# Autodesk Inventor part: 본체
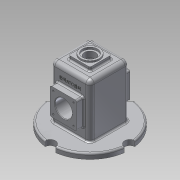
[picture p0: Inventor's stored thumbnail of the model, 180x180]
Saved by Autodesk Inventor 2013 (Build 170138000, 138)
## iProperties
Created: 2018-07
Part Number: 본체
Material: 알루미늄 6061
Document SubType Name: Modeling
Designer: Administrator
Mass: 1064.39 g
Surface Area: 1002.79 cm^2
Volume: 392.762 cm^3
Density: 2.71 g/cm^3
Author: Administrator
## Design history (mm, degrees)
sketch "스케치1"
  geometry: L1 (-37, -37)-(37, -37); L2 (37, -37)-(37, 37); L3 (37, 37)-(-37, 37); L4 (-37, 37)-(-37, -37); L5 (-37, -37)-(37, 37); L6 (37, -37)-(-37, 37); 1 further point
  constraints: 12 end point, 2 midpoint, 2 parallel, 1 horizontal, 1 perpendicular
  dimensions: "d0" = 74 distance of L2.end L3.end; "d2" = 74 distance of L1.end L2.end
extrude "돌출1" new body sketch "스케치1" distance "d3" = 110; taper "d4" = 0 deg
feature "쉘1" dims "d5" = 5
sketch "스케치2"
  geometry: L1 (0, 0)-(74, 0) reference; L2 (74, 0)-(74, 110) reference; L3 (12, 30)-(62, 30); L4 (62, 30)-(62, 80); L5 (62, 80)-(12, 80); L6 (12, 80)-(12, 30); L7 (12, 30)-(62, 80); L8 (62, 30)-(12, 80); 2 further points
  constraints: 12 end point, 2 midpoint, 2 parallel, 1 horizontal, 1 perpendicular
  dimensions: "d6" = 37 distance from line of L2 point (37, 55); "d7" = 55 distance from line of L1 point (37, 55); "d8" = 50 distance of L4.end L5.end; "d9" = 50 distance of L5.end L3.start
extrude "돌출2" join sketch "스케치2" distance "d10" = 13; taper "d11" = 0 deg
node "작업 평면1"
sketch "스케치3"
  geometry: L1 (20, -20)-(-20, -20); L2 (-20, -20)-(-20, 20); L3 (-20, 20)-(20, 20); L4 (20, 20)-(20, -20); L5 (20, -20)-(-20, 20); L6 (-20, -20)-(20, 20); 4 further points
  constraints: 12 end point, 4 midpoint, 2 coincident, 2 parallel, 1 horizontal, 1 perpendicular
  dimensions: "d12" = 40 distance of L1.end L2.end; "d14" = 40 distance of L2.end L3.end
extrude "돌출3" join sketch "스케치3" distance "d15" = 7; taper "d16" = 0 deg
sketch "스케치4"
  geometry: C1 r 17.5 at (0, 0); 1 further point
  constraints: 1 centre point, 1 coincident
  dimensions: "d17" = 35 diameter of C1
extrude "돌출4" join sketch "스케치4" distance "d19" = 3; taper "d20" = 0 deg
sketch "스케치5"
  geometry: C1 r 17.5 at (0, 0) reference; C2 r 14 at (0, 0)
  constraints: 1 centre point, 1 coincident
  dimensions: "d21" = 28 diameter of C2
extrude "돌출5" cut sketch "스케치5" distance "d23" = 4; taper "d24" = 0 deg
sketch "스케치6"
  geometry: C1 r 14 at (0, 0) reference; C2 r 10.5 at (0, 0)
  constraints: 1 centre point, 1 coincident
  dimensions: "d25" = 21 diameter of C2
extrude "돌출6" cut sketch "스케치6" stored distance "d27" = 4; taper "d28" = 0 deg
sketch "스케치7"
  geometry: L1 (62, 30)-(62, 80) reference; L2 (62, 80)-(12, 80) reference; L3 (12, 80)-(12, 30) reference; L4 (12, 80)-(12, 30) reference; L5 (12, 55)-(62, 55); C1 r 6 at (18, 74); C2 r 6 at (56, 74); C3 r 2 at (18, 74); C4 r 2 at (56, 74); C5 r 2 at (18, 36); C6 r 2 at (56, 36); 1 further point
  constraints: 6 centre point, 4 tangent, 2 coincident, 2 end point, 2 midpoint, 2 symmetric about line, 1 equal radius, 2 other
  dimensions: "d29" = 12 diameter of C1; "d31" = 12 diameter of C2; "d32" = 4 diameter of C3
hole "구멍1" sketch "스케치7" at (18, 74), (56, 74), (56, 36), (18, 36) diameter "d33" = 3.242; stored, may be unused: countersink angle "d37" = 90 deg, drill point angle "d39" = 118 deg; dims "d34" = 8, "d35" = 4, "d36" = 2, "d38" = 10
node "작업 평면2"
sketch "스케치8"
  geometry: L1 (-80, -13)-(-30, -13) reference; L2 (-55, -13)-(-55, 87); L3 (-80, 87)-(-30, 87) reference; L4 (0, 5)-(-105, 5) reference; L5 (0, 69)-(-105, 69) reference; L6 (-80, 5)-(-77.452, 12); L7 (-77.452, 12)-(-55, 12); L8 (-80, 69)-(-77.452, 62); L9 (-77.452, 62)-(-55, 62); L10 (-80, 5)-(-55, 5); L11 (-80, 69)-(-55, 69); 1 further point
  constraints: 14 end point, 8 point on line, 2 midpoint, 2 perpendicular
  dimensions: "d40" = 110 deg angle of L4 L6; "d41" = 7 distance between parallel lines of L7 L4; "d42" = 50 diameter of L6.start L2; "d43" = 50 diameter of L8.start L2; "d44" = 7 distance between parallel lines of L9 L5; "d45" = 110 deg angle of L5 L8
revolve "회전1" sketch "스케치8" stored, may be unused: angle "d46" = 90 deg
sketch "스케치9"
  geometry: L1 (-37, 37)-(-37, -37) reference; L2 (-37, -37)-(37, -37) reference; L3 (37, 37)-(-37, 37) reference; L4 (37, -37)-(37, 37) reference; C1 r 75 at (0, 0); 1 further point
  constraints: 1 centre point, 1 coincident
  dimensions: "d47" = 150 diameter of C1
extrude "돌출7" join sketch "스케치9" distance "d49" = 10; taper "d50" = 0 deg
fillet "모깎기1" dims "d51" = 8
fillet "모깎기2" dims "d52" = 8
fillet "모깎기3" dims "d53" = 3
fillet "모깎기4" dims "d54" = 3
sketch "스케치10"
  geometry: L1 (74, 10)-(74, 102) reference; L2 (-38, 0)-(112, 0) reference; C1 r 16 at (37, 55); 1 further point
  constraints: 1 centre point
  dimensions: "d55" = 37 distance from line of L1 C1.centre; "d56" = 55 distance from line of L2 C1.centre; "d57" = 32 diameter of C1
extrude "돌출8" cut sketch "스케치10" stored distance "d58" = 10; taper "d59" = 0 deg
chamfer "모따기1" distance "d60" = 1; stored, may be unused: second distance "d61" = 2, angle "d62" = 45 deg
fillet "모깎기5" dims "d63" = 3
fillet "모깎기6" dims "d64" = 3
sketch "스케치11"
  geometry: C1 r 10 at (-75, 0); C2 r 10 at (0, 75); C3 r 10 at (0, -75); C4 r 10 at (75, 0); A1 r 75 centre (0, 0) between (-75, 0) and (0, 75) reference; A2 r 75 centre (0, 0) between (-75, 0) and (0, 75) reference
  constraints: 8 point on circle, 4 centre point, 3 equal radius, 2 horizontal alignment, 2 vertical alignment
  dimensions: "d65" = 20 diameter of C1
extrude "돌출9" cut sketch "스케치11" stored distance "d67" = 10; taper "d68" = 0 deg
fillet "모깎기7" dims "d69" = 3
fillet "모깎기8" dims "d70" = 3
fillet "모깎기9" dims "d71" = 3
fillet "모깎기10" dims "d72" = 3
sketch "스케치12"
  geometry: L1 (8.261, -8.998)-(49.739, -8.998); L2 (49.739, -8.998)-(49.739, -15.002); L3 (49.739, -15.002)-(8.261, -15.002); L4 (8.261, -15.002)-(8.261, -8.998); L5 (8.261, -12)-(49.739, -12); L6 (29, -8.998)-(29, -15.002); L7 (66, -89)-(66, 0) reference; L8 (46.5, 18)-(11.5, 18) reference; 1 further point
  constraints: 4 end point, 4 midpoint, 2 other
  dimensions: "d73" = 37 distance between parallel lines of L7 L6; "d74" = 30 distance between parallel lines of L8 L5
extrude "돌출10" join sketch "스케치12" distance "d75" = 0.5; taper "d76" = 0 deg
node "솔리드1"
mirror "대칭1"
mirror "대칭2"
